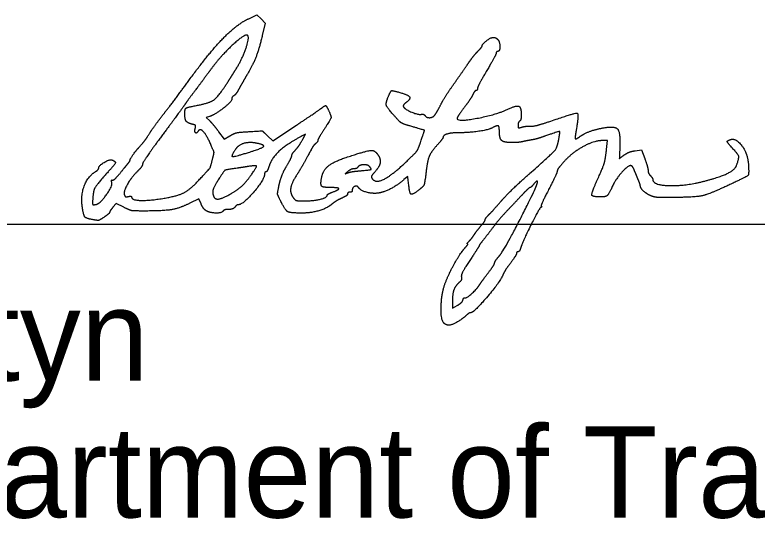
# Model space of a CAD drawing. Extents: x 0 to 34, y 0 to 22.
# Drawn here: x 26.127 to 27.265, y 8.102 to 8.915 of the extents above; entities that cross this region are included whole.
import ezdxf

# ---------------------------------------------------------------- set-up
doc = ezdxf.new("R2010")
doc.units = 0
for name, color, linetype in [('Default', 7, 'Continuous'), ('SH_Data', 7, 'Continuous'), ('SH_Text', 7, 'Continuous')]:
    doc.layers.add(name, color=color, linetype=linetype)

msp = doc.modelspace()

# ---------------------------------------------------------------- linework, layer by layer
at = {"layer": 'Default'}
for points in [[(26.4853, 8.9095), (26.4979, 8.9154), (26.5042, 8.909), (26.5106, 8.9026), (26.5062, 8.8839)], [(26.4253, 8.7595), (26.4203, 8.758), (26.4255, 8.7528)], [(26.5143, 8.7298), (26.5224, 8.7222), (26.5587, 8.7463)], [(26.4392, 8.7361), (26.4477, 8.7246), (26.4565, 8.7298)], [(26.5682, 8.7246), (26.5726, 8.7325), (26.5671, 8.7296)], [(27.034, 8.7087), (27.0355, 8.7225), (27.0277, 8.7225)], [(27.0779, 8.707), (27.0876, 8.7086), (27.0926, 8.695)], [(26.73, 8.6609), (26.7293, 8.6677), (26.7234, 8.6626)], [(26.4123, 8.6253), (26.409, 8.6333), (26.3951, 8.6265)], [(26.2937, 8.6202), (26.2822, 8.626), (26.2771, 8.6202)], [(26.7977, 8.4748), (26.7977, 8.4654), (26.8052, 8.4697)]]:
    msp.add_lwpolyline(points, dxfattribs=at)
for points in [[(26.3957, 8.8176), (26.4254, 8.8582), (26.4672, 8.9011), (26.4853, 8.9095)], [(26.4838, 8.8837), (26.4802, 8.8874), (26.4416, 8.8516), (26.4262, 8.8303)], [(26.4655, 8.8317), (26.4749, 8.8465), (26.4869, 8.8806), (26.4838, 8.8837)], [(26.5062, 8.8839), (26.5012, 8.8628), (26.492, 8.8392), (26.4826, 8.8233)], [(26.8433, 8.8676), (26.8433, 8.8704), (26.8565, 8.8807), (26.8602, 8.8808)], [(26.8602, 8.8808), (26.8623, 8.8808), (26.8652, 8.8796), (26.8668, 8.878)], [(26.8668, 8.878), (26.8703, 8.8745), (26.8707, 8.8593), (26.8673, 8.8593)], [(26.8229, 8.8423), (26.8269, 8.8481), (26.8331, 8.8558), (26.8367, 8.8595)], [(26.8367, 8.8595), (26.8403, 8.8631), (26.8433, 8.8668), (26.8433, 8.8676)], [(26.8649, 8.8567), (26.8649, 8.8554), (26.8584, 8.8433), (26.8505, 8.8299)], [(26.8673, 8.8593), (26.866, 8.8593), (26.8649, 8.8581), (26.8649, 8.8567)], [(26.8013, 8.8113), (26.8092, 8.8225), (26.819, 8.8364), (26.8229, 8.8423)], [(26.4262, 8.8303), (26.4226, 8.8254), (26.4132, 8.8127), (26.4053, 8.8022)], [(26.455, 8.815), (26.4583, 8.8202), (26.463, 8.8277), (26.4655, 8.8317)], [(26.4826, 8.8233), (26.4791, 8.8173), (26.4739, 8.8081), (26.471, 8.8029)], [(26.8505, 8.8299), (26.8426, 8.8165), (26.8361, 8.8041), (26.8361, 8.8024)], [(26.3555, 8.7642), (26.3644, 8.7755), (26.3825, 8.7996), (26.3957, 8.8176)], [(26.4052, 8.7763), (26.4258, 8.7801), (26.4398, 8.791), (26.455, 8.815)], [(26.7799, 8.7777), (26.7837, 8.7849), (26.7933, 8.8), (26.8013, 8.8113)], [(26.4053, 8.8022), (26.3974, 8.7917), (26.3893, 8.7807), (26.3873, 8.7778)], [(26.471, 8.8029), (26.4682, 8.7976), (26.4644, 8.7924), (26.4626, 8.7913)], [(26.8361, 8.8024), (26.8361, 8.8007), (26.8352, 8.7993), (26.8341, 8.7993)], [(26.4626, 8.7913), (26.4608, 8.7903), (26.4593, 8.7879), (26.4593, 8.7859)], [(26.709, 8.7601), (26.6975, 8.7732), (26.6953, 8.7799), (26.6992, 8.7895)], [(26.6992, 8.7895), (26.703, 8.7986), (26.7061, 8.7996), (26.7188, 8.7958)], [(26.7188, 8.7958), (26.7308, 8.7923), (26.7337, 8.7861), (26.726, 8.7803)], [(26.8288, 8.7927), (26.8271, 8.789), (26.8209, 8.7799), (26.8152, 8.7725)], [(26.8341, 8.7993), (26.833, 8.7993), (26.8306, 8.7963), (26.8288, 8.7927)], [(26.3873, 8.7778), (26.3853, 8.7748), (26.37, 8.7539), (26.3532, 8.7312)], [(26.4593, 8.7859), (26.4593, 8.7822), (26.4335, 8.7621), (26.4253, 8.7595)], [(26.726, 8.7803), (26.7233, 8.7782), (26.7218, 8.7753), (26.7228, 8.774)], [(26.7706, 8.7615), (26.7719, 8.7631), (26.7761, 8.7704), (26.7799, 8.7777)], [(26.3873, 8.7642), (26.3873, 8.7711), (26.3914, 8.7738), (26.4052, 8.7763)], [(26.5587, 8.7463), (26.5786, 8.7596), (26.5962, 8.7715), (26.5978, 8.7728)], [(26.5978, 8.7728), (26.6023, 8.7766), (26.6047, 8.7757), (26.6077, 8.7691)], [(26.6077, 8.7691), (26.6121, 8.7595), (26.6111, 8.7554), (26.6009, 8.7395)], [(26.7228, 8.774), (26.7254, 8.7702), (26.7453, 8.762), (26.75, 8.7628)], [(26.8152, 8.7725), (26.8096, 8.765), (26.8049, 8.7577), (26.8049, 8.7564)], [(26.8049, 8.7564), (26.8049, 8.7511), (26.8645, 8.7621), (26.8825, 8.7706)], [(26.8825, 8.7706), (26.8955, 8.7768), (26.9033, 8.7737), (26.9033, 8.7623)], [(26.334, 8.7348), (26.337, 8.7396), (26.3467, 8.7528), (26.3555, 8.7642)], [(26.3983, 8.7478), (26.3911, 8.7496), (26.3873, 8.7553), (26.3873, 8.7642)], [(26.7325, 8.7449), (26.7217, 8.7481), (26.7168, 8.7512), (26.709, 8.7601)], [(26.75, 8.7628), (26.7522, 8.7632), (26.7548, 8.7624), (26.7556, 8.761)], [(26.7556, 8.761), (26.7578, 8.7575), (26.7678, 8.7578), (26.7706, 8.7615)], [(26.9033, 8.7623), (26.9033, 8.7577), (26.9022, 8.7533), (26.9009, 8.7525)], [(26.9456, 8.7515), (26.986, 8.7654), (26.9919, 8.7638), (26.9878, 8.7399)], [(26.4034, 8.7416), (26.4043, 8.7451), (26.4031, 8.7466), (26.3983, 8.7478)], [(26.4255, 8.7528), (26.4283, 8.75), (26.4345, 8.7425), (26.4392, 8.7361)], [(26.7493, 8.7212), (26.755, 8.738), (26.7546, 8.7386), (26.7325, 8.7449)], [(26.8697, 8.7371), (26.8697, 8.7444), (26.866, 8.746), (26.8583, 8.7418)], [(26.9009, 8.7525), (26.8996, 8.7516), (26.8985, 8.7488), (26.8985, 8.7462)], [(26.8985, 8.7462), (26.8985, 8.7422), (26.8995, 8.7417), (26.9039, 8.7431)], [(26.9039, 8.7431), (26.9069, 8.744), (26.9127, 8.7447), (26.9168, 8.7445)], [(26.9168, 8.7445), (26.921, 8.7443), (26.9339, 8.7475), (26.9456, 8.7515)], [(26.9938, 8.7291), (27.001, 8.7341), (27.0192, 8.7404), (27.0329, 8.7426)], [(27.0329, 8.7426), (27.0476, 8.7449), (27.0552, 8.7345), (27.0544, 8.7132)], [(26.3177, 8.7129), (26.3243, 8.7203), (26.3285, 8.726), (26.334, 8.7348)], [(26.3532, 8.7312), (26.3364, 8.7086), (26.3226, 8.6884), (26.3225, 8.6865)], [(26.4077, 8.7368), (26.4052, 8.7329), (26.402, 8.7364), (26.4034, 8.7416)], [(26.4265, 8.7182), (26.4203, 8.7319), (26.4106, 8.7415), (26.4077, 8.7368)], [(26.4565, 8.7298), (26.463, 8.7337), (26.4706, 8.7354), (26.4857, 8.7363)], [(26.4857, 8.7363), (26.506, 8.7375), (26.5062, 8.7374), (26.5143, 8.7298)], [(26.6009, 8.7395), (26.5956, 8.7314), (26.5913, 8.7238), (26.5913, 8.7227)], [(26.8075, 8.7345), (26.796, 8.7345), (26.7833, 8.7307), (26.7833, 8.7273)], [(26.8583, 8.7418), (26.8527, 8.7388), (26.8225, 8.7345), (26.8075, 8.7345)], [(26.889, 8.7195), (26.8766, 8.7195), (26.8697, 8.7258), (26.8697, 8.7371)], [(26.9609, 8.7249), (26.963, 8.7364), (26.9613, 8.7368), (26.9403, 8.7296)], [(26.9878, 8.7399), (26.9865, 8.7323), (26.9857, 8.7257), (26.9862, 8.7252)], [(26.5671, 8.7296), (26.5437, 8.717), (26.521, 8.6964), (26.5168, 8.6839)], [(26.5554, 8.7064), (26.5608, 8.7124), (26.5633, 8.716), (26.5682, 8.7246)], [(26.5913, 8.7227), (26.5913, 8.7216), (26.5897, 8.7193), (26.5877, 8.7177)], [(26.731, 8.6939), (26.7414, 8.7039), (26.7455, 8.7101), (26.7493, 8.7212)], [(26.7833, 8.7273), (26.7833, 8.7264), (26.7791, 8.721), (26.7739, 8.7152)], [(26.9057, 8.7209), (26.9024, 8.7201), (26.8949, 8.7195), (26.889, 8.7195)], [(26.9189, 8.7235), (26.9149, 8.7228), (26.909, 8.7217), (26.9057, 8.7209)], [(26.9161, 8.6719), (26.9516, 8.7035), (26.9585, 8.7117), (26.9609, 8.7249)], [(26.9403, 8.7296), (26.9325, 8.7269), (26.9229, 8.7241), (26.9189, 8.7235)], [(27.0277, 8.7225), (27.015, 8.7225), (26.9812, 8.704), (26.9691, 8.6905)], [(26.9862, 8.7252), (26.9867, 8.7247), (26.9901, 8.7265), (26.9938, 8.7291)], [(27.2245, 8.7138), (27.2192, 8.7195), (27.219, 8.7222), (27.2236, 8.7239)], [(27.2236, 8.7239), (27.2322, 8.7272), (27.2506, 8.7023), (27.2516, 8.686)], [(26.3033, 8.6925), (26.3033, 8.6941), (26.3124, 8.7071), (26.3177, 8.7129)], [(26.4298, 8.6937), (26.4323, 8.7035), (26.432, 8.7057), (26.4265, 8.7182)], [(26.4649, 8.709), (26.4579, 8.6983), (26.4625, 8.6975), (26.4869, 8.705)], [(26.4975, 8.7185), (26.4866, 8.7207), (26.4693, 8.7156), (26.4649, 8.709)], [(26.4869, 8.705), (26.5061, 8.7109), (26.5101, 8.716), (26.4975, 8.7185)], [(26.5809, 8.7084), (26.5727, 8.693), (26.5649, 8.6792), (26.5588, 8.6695)], [(26.5877, 8.7177), (26.5858, 8.7161), (26.5827, 8.7119), (26.5809, 8.7084)], [(26.7739, 8.7152), (26.7655, 8.7058), (26.7597, 8.6932), (26.7581, 8.6805)], [(27.0194, 8.6608), (27.0284, 8.6807), (27.0324, 8.6939), (27.034, 8.7087)], [(27.0544, 8.7132), (27.0537, 8.6948), (27.0536, 8.6951), (27.0613, 8.7006)], [(27.2336, 8.6847), (27.2376, 8.6965), (27.236, 8.7014), (27.2245, 8.7138)], [(26.5429, 8.6823), (26.5473, 8.69), (26.5512, 8.6977), (26.5514, 8.6994)], [(26.5514, 8.6994), (26.5517, 8.7012), (26.5535, 8.7043), (26.5554, 8.7064)], [(26.6347, 8.6967), (26.6665, 8.7073), (26.6799, 8.7077), (26.685, 8.6983)], [(26.685, 8.6983), (26.6882, 8.6922), (26.6848, 8.6808), (26.6774, 8.6729)], [(27.0613, 8.7006), (27.0651, 8.7033), (27.0726, 8.7062), (27.0779, 8.707)], [(26.2553, 8.6804), (26.2554, 8.6842), (26.2721, 8.6942), (26.2759, 8.6927)], [(26.2759, 8.6927), (26.2819, 8.6904), (26.2796, 8.6855), (26.2653, 8.6696)], [(26.2888, 8.6733), (26.2941, 8.6799), (26.2996, 8.6866), (26.3009, 8.6882)], [(26.3009, 8.6882), (26.3022, 8.6898), (26.3033, 8.6917), (26.3033, 8.6925)], [(26.3225, 8.6865), (26.3224, 8.6845), (26.3191, 8.6797), (26.3151, 8.6757)], [(26.4101, 8.6632), (26.4262, 8.6807), (26.4265, 8.6813), (26.4298, 8.6937)], [(26.5971, 8.6656), (26.5992, 8.6769), (26.6154, 8.6903), (26.6347, 8.6967)], [(26.6708, 8.6825), (26.668, 8.6859), (26.6546, 8.6851), (26.6523, 8.6814)], [(26.674, 8.665), (26.6793, 8.6564), (26.7061, 8.6699), (26.731, 8.6939)], [(26.9691, 8.6905), (26.9632, 8.684), (26.9585, 8.6775), (26.9585, 8.6759)], [(27.0926, 8.695), (27.0954, 8.6876), (27.0977, 8.6794), (27.0977, 8.6769)], [(27.2516, 8.686), (27.2526, 8.6707), (27.2499, 8.6676), (27.2265, 8.6566)], [(26.2304, 8.6188), (26.2275, 8.6373), (26.2382, 8.6674), (26.2506, 8.6751)], [(26.2506, 8.6751), (26.2532, 8.6767), (26.2553, 8.6791), (26.2553, 8.6804)], [(26.3151, 8.6757), (26.3053, 8.6661), (26.2929, 8.644), (26.2947, 8.6393)], [(26.4677, 8.6802), (26.4499, 8.6776), (26.4479, 8.6765), (26.4406, 8.6653)], [(26.4851, 8.6829), (26.4795, 8.682), (26.4717, 8.6808), (26.4677, 8.6802)], [(26.4901, 8.6712), (26.4979, 8.6826), (26.497, 8.6847), (26.4851, 8.6829)], [(26.5117, 8.6745), (26.5106, 8.6745), (26.5097, 8.6731), (26.5097, 8.6715)], [(26.5168, 8.6839), (26.5151, 8.6787), (26.5128, 8.6745), (26.5117, 8.6745)], [(26.532, 8.6545), (26.5336, 8.6622), (26.5385, 8.6747), (26.5429, 8.6823)], [(26.638, 8.6755), (26.6334, 8.6717), (26.6334, 8.6717), (26.6381, 8.6734)], [(26.6468, 8.6793), (26.6445, 8.6793), (26.6405, 8.6775), (26.638, 8.6755)], [(26.6381, 8.6734), (26.6407, 8.6743), (26.6483, 8.6755), (26.6549, 8.6761)], [(26.6523, 8.6814), (26.6516, 8.6802), (26.6491, 8.6793), (26.6468, 8.6793)], [(26.6549, 8.6761), (26.6716, 8.6776), (26.674, 8.6786), (26.6708, 8.6825)], [(26.7581, 8.6805), (26.7553, 8.658), (26.7536, 8.6525), (26.7479, 8.648)], [(26.9585, 8.6759), (26.9585, 8.6743), (26.9525, 8.6615), (26.9453, 8.6473)], [(27.0709, 8.6841), (27.0666, 8.6841), (27.0483, 8.6636), (27.0436, 8.6534)], [(27.0765, 8.6775), (27.075, 8.6811), (27.0725, 8.6841), (27.0709, 8.6841)], [(27.0824, 8.6633), (27.0806, 8.6675), (27.078, 8.6738), (27.0765, 8.6775)], [(27.0977, 8.6769), (27.0977, 8.6744), (27.0993, 8.6708), (27.1013, 8.6688)], [(27.1847, 8.6605), (27.2084, 8.6667), (27.2314, 8.6781), (27.2336, 8.6847)], [(26.2653, 8.6696), (26.2516, 8.6545), (26.2466, 8.6443), (26.246, 8.6305)], [(26.2765, 8.662), (26.2779, 8.6616), (26.2834, 8.6667), (26.2888, 8.6733)], [(26.3536, 8.6338), (26.3763, 8.6375), (26.3959, 8.6477), (26.4101, 8.6632)], [(26.4406, 8.6653), (26.4324, 8.6526), (26.4292, 8.6428), (26.4315, 8.637)], [(26.4602, 8.6425), (26.4714, 8.6495), (26.4824, 8.6601), (26.4901, 8.6712)], [(26.5097, 8.6715), (26.5095, 8.6629), (26.4764, 8.6241), (26.4693, 8.6241)], [(26.5588, 8.6695), (26.5508, 8.6569), (26.5486, 8.6417), (26.5537, 8.6349)], [(26.6106, 8.6505), (26.5991, 8.6505), (26.5951, 8.655), (26.5971, 8.6656)], [(26.6774, 8.6729), (26.6746, 8.67), (26.6731, 8.6665), (26.674, 8.665)], [(26.872, 8.6292), (26.8792, 8.6376), (26.899, 8.6568), (26.9161, 8.6719)], [(27.0858, 8.6537), (27.0857, 8.6548), (27.0842, 8.6591), (27.0824, 8.6633)], [(27.1013, 8.6688), (27.1033, 8.6668), (27.1049, 8.6641), (27.1049, 8.6628)], [(27.1049, 8.6628), (27.1049, 8.6543), (27.1555, 8.6528), (27.1847, 8.6605)], [(26.2509, 8.6245), (26.2572, 8.6254), (26.2773, 8.6539), (26.2753, 8.6591)], [(26.2753, 8.6591), (26.2745, 8.661), (26.2751, 8.6623), (26.2765, 8.662)], [(26.534, 8.6305), (26.5296, 8.6396), (26.5294, 8.6418), (26.532, 8.6545)], [(26.6536, 8.6506), (26.6516, 8.6539), (26.6441, 8.6507), (26.6441, 8.6466)], [(26.7234, 8.6626), (26.714, 8.6544), (26.694, 8.6438), (26.6849, 8.6421)], [(26.7479, 8.648), (26.7362, 8.6388), (26.7318, 8.6419), (26.73, 8.6609)], [(26.8694, 8.5454), (26.8771, 8.5541), (26.9303, 8.6579), (26.9282, 8.6599)], [(26.9225, 8.6559), (26.9201, 8.6529), (26.9175, 8.6505), (26.9167, 8.6505)], [(26.9282, 8.6599), (26.9275, 8.6607), (26.9249, 8.6588), (26.9225, 8.6559)], [(27.0267, 8.6361), (27.0122, 8.6361), (27.0106, 8.6415), (27.0194, 8.6608)], [(27.0436, 8.6534), (27.0379, 8.641), (27.0331, 8.6361), (27.0267, 8.6361)], [(27.1014, 8.6381), (27.0944, 8.6415), (27.0859, 8.6499), (27.0858, 8.6537)], [(27.2265, 8.6566), (27.1917, 8.6403), (27.1707, 8.6355), (27.1313, 8.6351)], [(26.4315, 8.637), (26.4335, 8.6317), (26.4471, 8.6344), (26.4602, 8.6425)], [(26.6057, 8.6387), (26.6057, 8.6397), (26.6094, 8.6419), (26.614, 8.6435)], [(26.614, 8.6435), (26.6243, 8.6473), (26.6227, 8.6505), (26.6106, 8.6505)], [(26.6369, 8.6408), (26.6369, 8.6394), (26.6345, 8.6372), (26.6315, 8.6359)], [(26.6405, 8.6433), (26.6385, 8.6433), (26.6369, 8.6422), (26.6369, 8.6408)], [(26.6441, 8.6466), (26.6441, 8.6448), (26.6425, 8.6433), (26.6405, 8.6433)], [(26.6849, 8.6421), (26.6763, 8.6406), (26.6565, 8.6459), (26.6536, 8.6506)], [(26.9079, 8.6427), (26.9038, 8.6384), (26.8933, 8.6273), (26.8845, 8.618)], [(26.9167, 8.6505), (26.916, 8.6505), (26.912, 8.6469), (26.9079, 8.6427)], [(26.9453, 8.6473), (26.938, 8.6332), (26.9329, 8.6216), (26.9339, 8.6216)], [(26.246, 8.6305), (26.2458, 8.6249), (26.2466, 8.6239), (26.2509, 8.6245)], [(26.2947, 8.6393), (26.2956, 8.6369), (26.2979, 8.636), (26.3009, 8.6368)], [(26.3009, 8.6368), (26.3035, 8.6374), (26.3057, 8.6371), (26.3057, 8.636)], [(26.3057, 8.636), (26.3057, 8.6314), (26.3313, 8.6302), (26.3536, 8.6338)], [(26.5658, 8.6113), (26.5483, 8.6114), (26.5413, 8.6157), (26.534, 8.6305)], [(26.5537, 8.6349), (26.5566, 8.6311), (26.5601, 8.6301), (26.5713, 8.6301)], [(26.5713, 8.6301), (26.5853, 8.6301), (26.6057, 8.6352), (26.6057, 8.6387)], [(26.6315, 8.6359), (26.6242, 8.6326), (26.6165, 8.6281), (26.6123, 8.6246)], [(26.8535, 8.6088), (26.8565, 8.6116), (26.8648, 8.6208), (26.872, 8.6292)], [(27.1313, 8.6351), (27.1164, 8.6349), (27.1061, 8.636), (27.1014, 8.6381)], [(26.247, 8.6011), (26.2361, 8.6031), (26.2323, 8.6072), (26.2304, 8.6188)], [(26.2771, 8.6202), (26.2744, 8.617), (26.2721, 8.6136), (26.2721, 8.6126)], [(26.3245, 8.6145), (26.3089, 8.6145), (26.303, 8.6156), (26.2937, 8.6202)], [(26.3951, 8.6265), (26.3796, 8.6187), (26.3544, 8.6145), (26.3245, 8.6145)], [(26.4205, 8.6147), (26.4179, 8.6161), (26.4142, 8.6209), (26.4123, 8.6253)], [(26.4641, 8.6205), (26.4625, 8.6185), (26.4581, 8.6169), (26.4543, 8.6169)], [(26.4693, 8.6241), (26.4681, 8.6241), (26.4657, 8.6224), (26.4641, 8.6205)], [(26.6123, 8.6246), (26.6046, 8.6182), (26.5803, 8.6113), (26.5658, 8.6113)], [(26.8845, 8.618), (26.8757, 8.6087), (26.8658, 8.5975), (26.8625, 8.593)], [(26.9331, 8.6198), (26.9304, 8.618), (26.9052, 8.567), (26.9022, 8.5575)], [(26.9339, 8.6216), (26.9349, 8.6216), (26.9345, 8.6208), (26.9331, 8.6198)], [(26.2721, 8.6126), (26.2721, 8.6117), (26.2683, 8.6083), (26.2637, 8.6052)], [(26.4461, 8.6145), (26.4441, 8.6113), (26.4266, 8.6114), (26.4205, 8.6147)], [(26.4543, 8.6169), (26.4506, 8.6169), (26.4469, 8.6158), (26.4461, 8.6145)], [(26.8481, 8.6016), (26.8482, 8.6027), (26.8506, 8.606), (26.8535, 8.6088)], [(26.2637, 8.6052), (26.2572, 8.6007), (26.2536, 8.5998), (26.247, 8.6011)], [(26.8415, 8.5918), (26.8451, 8.596), (26.8481, 8.6004), (26.8481, 8.6016)], [(26.8313, 8.5784), (26.8333, 8.5815), (26.8379, 8.5875), (26.8415, 8.5918)], [(26.8625, 8.593), (26.8544, 8.5821), (26.8439, 8.5683), (26.8409, 8.5648)], [(26.8235, 8.5685), (26.8258, 8.5709), (26.8293, 8.5754), (26.8313, 8.5784)], [(26.8176, 8.5587), (26.8203, 8.5616), (26.8218, 8.5641), (26.8209, 8.5641)], [(26.8209, 8.5641), (26.82, 8.5641), (26.8212, 8.566), (26.8235, 8.5685)], [(26.8385, 8.5609), (26.8385, 8.5603), (26.8322, 8.5504), (26.8244, 8.5388)], [(26.8409, 8.5648), (26.8396, 8.5632), (26.8385, 8.5614), (26.8385, 8.5609)], [(26.7875, 8.5061), (26.7934, 8.5209), (26.8105, 8.5508), (26.8176, 8.5587)], [(26.8961, 8.5496), (26.8961, 8.5482), (26.8918, 8.5414), (26.8866, 8.5345)], [(26.8983, 8.5521), (26.8971, 8.5521), (26.8961, 8.5509), (26.8961, 8.5496)], [(26.9022, 8.5575), (26.9013, 8.5545), (26.8996, 8.5521), (26.8983, 8.5521)], [(26.8244, 8.5388), (26.8158, 8.5257), (26.8108, 8.516), (26.8115, 8.5133)], [(26.8625, 8.5351), (26.8625, 8.5364), (26.8656, 8.541), (26.8694, 8.5454)], [(26.8523, 8.5192), (26.8579, 8.5266), (26.8625, 8.5337), (26.8625, 8.5351)], [(26.8866, 8.5345), (26.8814, 8.5276), (26.8763, 8.5196), (26.8752, 8.5168)], [(26.8752, 8.5168), (26.8716, 8.5069), (26.8304, 8.4585), (26.8257, 8.4585)], [(26.8397, 8.502), (26.841, 8.5041), (26.8467, 8.5119), (26.8523, 8.5192)], [(26.7857, 8.4416), (26.7798, 8.4454), (26.781, 8.4897), (26.7875, 8.5061)], [(26.8078, 8.5047), (26.8019, 8.4994), (26.7977, 8.4871), (26.7977, 8.4748)], [(26.8115, 8.5133), (26.8122, 8.5107), (26.8106, 8.5071), (26.8078, 8.5047)], [(26.8169, 8.4813), (26.8188, 8.4801), (26.8355, 8.4952), (26.8397, 8.502)], [(26.8139, 8.4782), (26.8145, 8.4805), (26.8159, 8.4819), (26.8169, 8.4813)], [(26.8052, 8.4697), (26.8094, 8.4721), (26.8133, 8.4759), (26.8139, 8.4782)], [(26.8257, 8.4585), (26.8243, 8.4585), (26.821, 8.4564), (26.8183, 8.4539)], [(26.8183, 8.4539), (26.8121, 8.4482), (26.7961, 8.4392), (26.7922, 8.4393)], [(26.7922, 8.4393), (26.7906, 8.4393), (26.7877, 8.4404), (26.7857, 8.4416)]]:
    msp.add_open_spline(points, degree=2, dxfattribs=at)
at = {"layer": 'SH_Data'}
msp.add_line((25, 8.5943), (28.5, 8.5943), dxfattribs=at)

# ---------------------------------------------------------------- texts
at = {"layer": 'SH_Text'}
for s, p in [('Pamela Boratyn', (25, 8.3543)), ('Director, Department of Transportation', (25, 8.1443))]:
    msp.add_text(s, height=0.14, dxfattribs=at).set_placement(p)

doc.saveas('drawing.dxf')
